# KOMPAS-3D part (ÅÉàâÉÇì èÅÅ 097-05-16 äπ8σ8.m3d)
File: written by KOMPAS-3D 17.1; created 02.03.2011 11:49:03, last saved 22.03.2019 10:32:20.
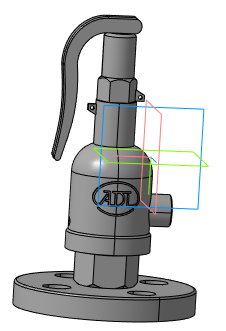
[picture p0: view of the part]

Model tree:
1. Плоскость XY
2. Плоскость ZX
3. Плоскость ZY
4. Ось X
5. Ось Y
6. Ось Z
7. Начало координат
8. Операция без истории:2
